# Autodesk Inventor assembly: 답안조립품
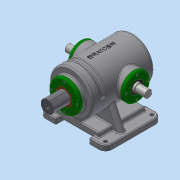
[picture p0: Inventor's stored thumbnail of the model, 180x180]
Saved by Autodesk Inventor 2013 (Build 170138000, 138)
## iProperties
Created: 2018-06
Part Number: 답안조립품
Document SubType Name: Assembly
Designer: Administrator
Mass: 8560.47 g
Surface Area: 4294.68 cm^2
Volume: 2307.06 cm^3
Density: 3.71055 g/cm^3
Author: Administrator
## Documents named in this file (13)
- C:\Users\Administrator\Desktop\380628V1010\답안조립품.iam
- C:\Users\Administrator\Desktop\380628V1010\본체.ipt
- C:\Users\Administrator\Desktop\380628V1010\가변스프링.ipt
- C:\Users\Administrator\Desktop\380628V1010\베어링 6205.ipt
- 베어링 6205.ipt
- C:\Users\Administrator\Desktop\380628V1010\볼트 M4.ipt
- C:\Users\Administrator\Desktop\380628V1010\부시.ipt
- C:\Users\Administrator\Desktop\380628V1010\슬라이드 커버.ipt
- C:\Users\Administrator\Desktop\380628V1010\슬라이드.ipt
- C:\Users\Administrator\Desktop\380628V1010\오일실.ipt
- 오일실.ipt
- C:\Users\Administrator\Desktop\380628V1010\축 커버.ipt
- C:\Users\Administrator\Desktop\380628V1010\편심축.ipt
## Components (1 placed, 1 different names)
1. 가변스프링:1
